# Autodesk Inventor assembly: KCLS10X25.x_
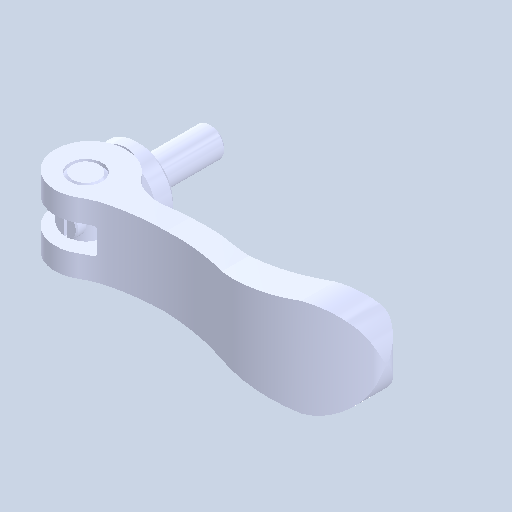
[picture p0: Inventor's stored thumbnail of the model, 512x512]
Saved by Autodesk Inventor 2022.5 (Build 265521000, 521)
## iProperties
Created: 2024-08
Part Number: KCLS10X25.x_
Document SubType Name: Assembly
Designer: ImaoCorp
Author: ImaoCorp
Sending System: SOLIDWORKS 2022-2022290
MC: AMD64
MC_MODEL: Intel64 Family 6 Model 60 Stepping 3, GenuineIntel
OS: Windows_NT
FRU: Parasolid Version 33.1, build 260,  4-25-2022
FORMAT: text
GUISE: transmit
KEY: FILEKCLS10X25.x_t
DATE: Thu Aug 29 10:55:16 2024
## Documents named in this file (5)
- Y:\5.更新分\2024年対応\1001_KCL\データ\kcls10x25\KCLS10X25.x_.iam
- Y:\5.更新分\2024年対応\1001_KCL\データ\kcls10x25\KCLS10X25_01.ipt
- Y:\5.更新分\2024年対応\1001_KCL\データ\kcls10x25\KCLS10X25_02.ipt
- Y:\5.更新分\2024年対応\1001_KCL\データ\kcls10x25\KCLS10X25_03.ipt
- Y:\5.更新分\2024年対応\1001_KCL\データ\kcls10x25\KCLS10X25_04.ipt
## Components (4 placed, 4 different names)
1. KCLS10X25_01
2. KCLS10X25_02
3. KCLS10X25_03
4. KCLS10X25_04
